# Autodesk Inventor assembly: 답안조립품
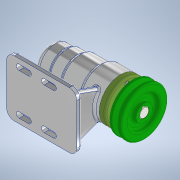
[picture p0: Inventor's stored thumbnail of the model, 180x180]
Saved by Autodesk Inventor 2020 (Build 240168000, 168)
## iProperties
Created: 2021-10
Part Number: 답안조립품
Document SubType Name: Assembly
Designer: user
Author: user
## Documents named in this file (12)
- C:\Users\user\Desktop\711007V1012\답안조립품.iam
- C:\Users\user\Desktop\711007V1012\V벨트풀리.ipt
- C:\Users\user\Desktop\711007V1012\멈춤나사 M3.ipt
- C:\Users\user\Desktop\711007V1012\베어링 6004.ipt
- C:\Users\user\Desktop\711007V1012\베어링 51202.ipt
- C:\Users\user\Desktop\711007V1012\본체.ipt
- C:\Users\user\Desktop\711007V1012\볼트 M4.ipt
- C:\Users\user\Desktop\711007V1012\어댑터슬리브.ipt
- C:\Users\user\Desktop\711007V1012\오일 실 20x35x7.ipt
- C:\Users\user\Desktop\711007V1012\축.ipt
- C:\Users\user\Desktop\711007V1012\커버.ipt
- C:\Users\user\Desktop\711007V1012\키 5x5.ipt
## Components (1 placed, 1 different names)
1. V벨트풀리:1
